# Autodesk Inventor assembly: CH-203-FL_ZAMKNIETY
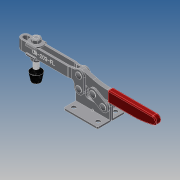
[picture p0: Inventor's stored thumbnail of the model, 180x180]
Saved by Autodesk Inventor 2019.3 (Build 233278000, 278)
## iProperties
Company: Î¢ÈíÖÐ¹ú
Created: 2012-09
Part Number: CH-203-FL_ZAMKNIETY
Material: Ogólny
Description: STEP AP203
Document SubType Name: Assembly
Designer: CADENGINEERING4
Sending System: SolidWorks 2010
Preprocessor: SwSTEP 2.0
Title: CH-203-FL.STEP
Author: Î¢ÈíÓÃ»§
Revision Number: ÈÎºÎ
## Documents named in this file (9)
- E:\STRONA\Horizontal toggle clamp\CH-203-FL\CH-203-FL_ZAMKNIETY.iam
- E:\STRONA\Horizontal toggle clamp\CH-203-FL\203-F-04.ipt
- E:\STRONA\Horizontal toggle clamp\CH-203-FL\225-D-06.ipt
- E:\STRONA\Horizontal toggle clamp\CH-203-FL\203-FL-02.ipt
- E:\STRONA\Horizontal toggle clamp\CH-203-FL\FW516.ipt
- E:\STRONA\Horizontal toggle clamp\CH-203-FL\203-F-01.ipt
- E:\STRONA\Horizontal toggle clamp\CH-203-FL\56212-02.ipt
- E:\STRONA\Horizontal toggle clamp\CH-203-FL\03.iam
- E:\STRONA\Horizontal toggle clamp\CH-203-FL\56212.ipt
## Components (14 placed, 14 different names)
1. 203-F-04_1 — Zestawiające:11, Zestawiające:13, Zestawiające:14
2. 203-F-04_2 — Zestawiające:10, Zestawiające:12, Zestawiające:13, Zestawiające:14, Zestawiające:15, Zestawiające:16, Zestawiające:17, Zestawiające:18, Zestawiające:20
3. 225-D-06_3 — Zestawiające:23, Zestawiające:24
4. 203-FL-02_4 — Równoległe:1, Zestawiające:6, Zestawiające:7, Zestawiające:9, Zestawiające:21, Zestawiające:22, Zestawiające:23, Zestawiające:24, Zestawiające:25, Zestawiające:26
5. FW516_5 — Równoległe:2, Zestawiające:2, Zestawiające:7, Zestawiające:8
6. 203-F-01_6 — Zestawiające:10, Zestawiające:11, Zestawiające:12, Zestawiające:21, Zestawiające:22, Przejściowe:1
7. 225-D-06_7 — Zestawiające:19, Zestawiające:20
8. 56212-02_8 — Zestawiające:1, Zestawiające:8
9. 56212-02_9 — Równoległe:3, Zestawiające:4, Zestawiające:5
10. 03_10 [sub-assembly] — Zestawiające:17, Zestawiające:18, Zestawiające:19, Zestawiające:27, Przejściowe:1
11. 225-D-06_11 — Zestawiające:25, Zestawiające:26, Zestawiające:27
12. FW516_12 — Równoległe:1, Równoległe:2, Zestawiające:3, Zestawiające:5, Zestawiające:6
13. 56212_13 — Równoległe:3, Zestawiające:1, Zestawiające:2, Zestawiające:3, Zestawiające:4, Zestawiające:9
14. 225-D-06_14 — Zestawiające:15, Zestawiające:16
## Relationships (31: Mate 27, Flush 3, Transitional 1)
- Równoległe:1 [Flush]: 203-FL-02_4 ↔ FW516_12
- Równoległe:2 [Flush]: FW516_5 ↔ FW516_12
- Równoległe:3 [Flush]: 56212-02_9 ↔ 56212_13
- Zestawiające:1 [Mate]: 56212-02_8 ↔ 56212_13
- Zestawiające:2 [Mate]: FW516_5 ↔ 56212_13
- Zestawiające:3 [Mate]: FW516_12 ↔ 56212_13
- Zestawiające:4 [Mate]: 56212-02_9 ↔ 56212_13
- Zestawiające:5 [Mate]: 56212-02_9 ↔ FW516_12
- Zestawiające:6 [Mate]: 203-FL-02_4 ↔ FW516_12
- Zestawiające:7 [Mate]: 203-FL-02_4 ↔ FW516_5
- Zestawiające:8 [Mate]: FW516_5 ↔ 56212-02_8
- Zestawiające:9 [Mate]: 203-FL-02_4 ↔ 56212_13
- Zestawiające:10 [Mate]: 203-F-04_2 ↔ 203-F-01_6
- Zestawiające:11 [Mate]: 203-F-04_1 ↔ 203-F-01_6
- Zestawiające:12 [Mate]: 203-F-04_2 ↔ 203-F-01_6
- Zestawiające:13 [Mate]: 203-F-04_1 ↔ 203-F-04_2
- Zestawiające:14 [Mate]: 203-F-04_1 ↔ 203-F-04_2
- Zestawiające:15 [Mate]: 203-F-04_2 ↔ 225-D-06_14
- Zestawiające:16 [Mate]: 203-F-04_2 ↔ 225-D-06_14
- Zestawiające:17 [Mate]: 203-F-04_2 ↔ 03_10
- Zestawiające:18 [Mate]: 203-F-04_2 ↔ 03_10
- Zestawiające:19 [Mate]: 225-D-06_7 ↔ 03_10
- Zestawiające:20 [Mate]: 203-F-04_2 ↔ 225-D-06_7
- Zestawiające:21 [Mate]: 203-FL-02_4 ↔ 203-F-01_6
- Zestawiające:22 [Mate]: 203-FL-02_4 ↔ 203-F-01_6
- Zestawiające:23 [Mate]: 225-D-06_3 ↔ 203-FL-02_4
- Zestawiające:24 [Mate]: 225-D-06_3 ↔ 203-FL-02_4
- Zestawiające:25 [Mate]: 203-FL-02_4 ↔ 225-D-06_11
- Zestawiające:26 [Mate]: 203-FL-02_4 ↔ 225-D-06_11
- Zestawiające:27 [Mate]: 03_10 ↔ 225-D-06_11
- Przejściowe:1 [Transitional]: 203-F-01_6 ↔ 03_10
